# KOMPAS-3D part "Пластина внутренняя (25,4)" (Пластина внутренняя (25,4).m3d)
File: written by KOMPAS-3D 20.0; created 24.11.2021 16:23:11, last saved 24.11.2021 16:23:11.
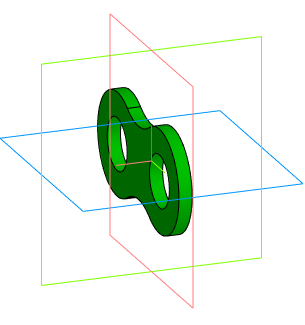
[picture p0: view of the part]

Document properties: Полное имя файла: C:\!WORK!\ЗИГ-18.240.00\Цепь\Пластина внутренняя (25,4).m3d

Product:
- Part/product: Пластина внутренняя (25,4)
    Материал: Сталь 45  ГОСТ 1050-2013 (density 7810 kg/m3)
    Масса: 0.0168549
  - Body: Тело 1
      Масса: 0.0169542

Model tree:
1. Эскиз:1
2. Элемент выдавливания:1  (labels: Сталь 45  ГОСТ 1050-2013)
     Расстояние 1 = 3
